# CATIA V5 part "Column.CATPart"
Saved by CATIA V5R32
Part number: Column
Bounding box of the stored display mesh (mm): x -75 to 75, y -75 to 75, z -500 to 500
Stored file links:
  D:\PROJECTS\Project 2022\CATIA V5 6R 2022\Resources\Part Files\c16_catia_v5_6r2022_prt\Revolute Joint-(Fig 16-3)\Column.CATPart
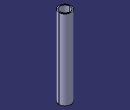
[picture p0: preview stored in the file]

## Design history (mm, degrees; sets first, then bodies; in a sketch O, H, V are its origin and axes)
Body1 (main body)
  Sketch1 on xy-plane, origin (0, 0, 0), H (1, 0, 0), V (0, 1, 0)
    circle A1 centre (0, 0) radius 62.5
    circle A2 centre (0, 0) radius 75
    radius A2 = 75
    radius A1 = 62.5
  Pad1: profile Sketch1, direction (0, 0, 1), length 500, mirrored extent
